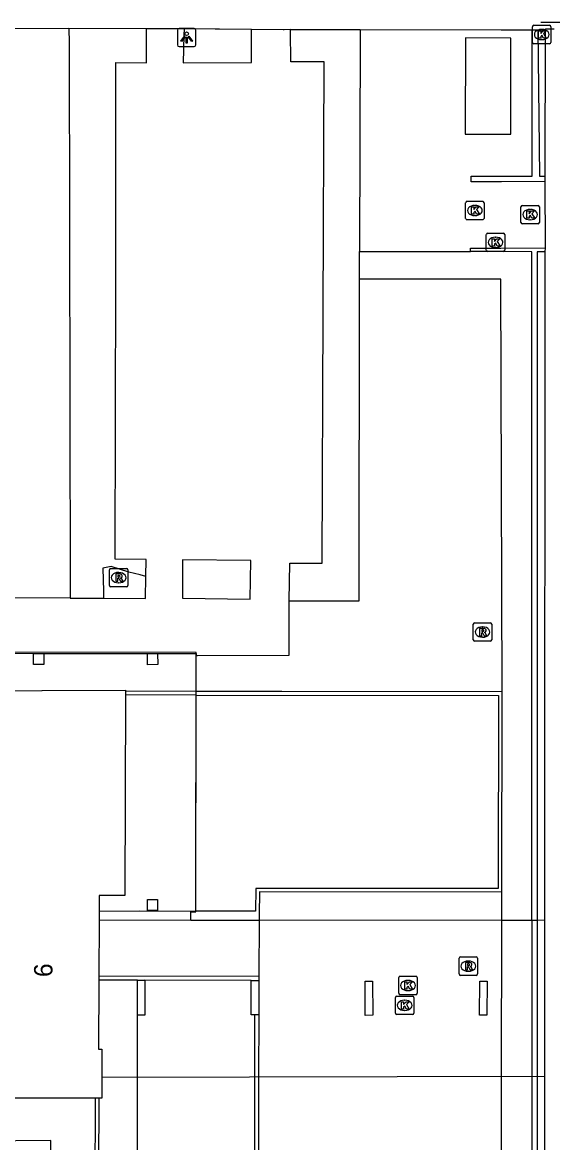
# Model space of a CAD drawing. Extents: x 161477 to 163040, y 383680 to 384868.
# Drawn here: x 161757.4 to 161786.3, y 384128.9 to 384189.9 of the extents above; entities that cross this region are included whole.
import ezdxf

# ---------------------------------------------------------------- set-up
doc = ezdxf.new("R2010")
doc.units = 0
for name, color, linetype in [('IMGEO_Groenvoorziening', 7, 'Continuous'), ('IMGEO_Kolk', 7, 'Continuous'), ('IMGEO_Lichtpunt', 7, 'Continuous'), ('IMGEO_Lijnafwatering', 7, 'Continuous'), ('IMGEO_Muur', 7, 'Continuous'), ('IMGEO_Pand', 7, 'Continuous'), ('IMGEO_Pand_nummerreeks', 7, 'Continuous'), ('IMGEO_Pand_overbouw', 7, 'Continuous'), ('IMGEO_Rijbaan_lokaal_gesloten', 7, 'Continuous'), ('IMGEO_Rijbaan_lokaal_open', 7, 'Continuous'), ('IMGEO_Rioolput', 7, 'Continuous'), ('IMGEO_Voetpad_gesloten', 7, 'Continuous'), ('IMGEO_Voetpad_open', 7, 'Continuous')]:
    doc.layers.add(name, color=color, linetype=linetype)

msp = doc.modelspace()

# ---------------------------------------------------------------- linework, layer by layer
at = {"layer": 'IMGEO_Groenvoorziening'}
for points in [[(161759.976, 384189.513), (161759.977, 384188.732), (161760.032, 384158.93), (161760.033, 384158.521)], [(161771.96, 384158.37), (161775.755, 384158.378), (161775.779, 384175.877)], [(161765.84, 384080.732), (161762.894, 384080.681), (161762.895, 384081.151), (161763.216, 384099.214), (161763.654, 384124.37), (161759.044, 384124.455), (161758.995, 384129.011), (161747.606, 384128.913), (161747.599, 384129.203)]]:
    msp.add_lwpolyline(points, dxfattribs=at)
at = {"layer": 'IMGEO_Kolk'}
for p, q in [((161785.189, 384188.766), (161785.189, 384189.618)), ((161785.264, 384189.692), (161786.116, 384189.692)), ((161786.19, 384189.618), (161786.19, 384188.766)), ((161785.7, 384188.912), (161785.675, 384188.912)), ((161785.677, 384189.472), (161785.702, 384189.472)), ((161786.116, 384188.692), (161785.264, 384188.692)), ((161781.553, 384179.19), (161781.553, 384180.042)), ((161781.628, 384180.116), (161782.48, 384180.116)), ((161782.041, 384179.896), (161782.066, 384179.896)), ((161782.554, 384180.042), (161782.554, 384179.19)), ((161784.562, 384178.969), (161784.562, 384179.821)), ((161784.637, 384179.895), (161785.489, 384179.895)), ((161785.563, 384179.821), (161785.563, 384178.969)), ((161782.064, 384179.336), (161782.039, 384179.336)), ((161785.05, 384179.675), (161785.075, 384179.675)), ((161782.48, 384179.116), (161781.628, 384179.116)), ((161785.489, 384178.895), (161784.637, 384178.895)), ((161785.073, 384179.115), (161785.048, 384179.115)), ((161782.677, 384177.454), (161782.677, 384178.306)), ((161782.752, 384178.38), (161783.604, 384178.38)), ((161783.165, 384178.16), (161783.19, 384178.16)), ((161783.678, 384178.306), (161783.678, 384177.454)), ((161783.604, 384177.38), (161782.752, 384177.38)), ((161783.188, 384177.6), (161783.163, 384177.6)), ((161777.916, 384137.022), (161777.916, 384137.874)), ((161777.991, 384137.948), (161778.843, 384137.948)), ((161778.404, 384137.728), (161778.429, 384137.728)), ((161778.917, 384137.874), (161778.917, 384137.022)), ((161778.427, 384137.168), (161778.402, 384137.168)), ((161777.734, 384135.941), (161777.734, 384136.793)), ((161777.809, 384136.867), (161778.661, 384136.867)), ((161778.843, 384136.948), (161777.991, 384136.948)), ((161778.222, 384136.647), (161778.247, 384136.647)), ((161778.735, 384136.793), (161778.735, 384135.941)), ((161778.661, 384135.867), (161777.809, 384135.867)), ((161778.245, 384136.087), (161778.22, 384136.087))]:
    msp.add_line(p, q, dxfattribs=at)
for points in [[(161785.189, 384188.766), (161785.189, 384189.618)], [(161785.264, 384189.692), (161786.116, 384189.692)], [(161786.19, 384189.618), (161786.19, 384188.766)], [(161785.51, 384189.392), (161785.633, 384189.392), (161785.633, 384189.241), (161785.763, 384189.392), (161785.927, 384189.392), (161785.781, 384189.241), (161785.934, 384188.992), (161785.782, 384188.992), (161785.697, 384189.156), (161785.633, 384189.089), (161785.633, 384188.992), (161785.51, 384188.992), (161785.51, 384189.392)], [(161786.116, 384188.692), (161785.264, 384188.692)], [(161781.553, 384179.19), (161781.553, 384180.042)], [(161781.628, 384180.116), (161782.48, 384180.116)], [(161781.874, 384179.816), (161781.997, 384179.816), (161781.997, 384179.665), (161782.127, 384179.816), (161782.291, 384179.816), (161782.145, 384179.665), (161782.298, 384179.416), (161782.146, 384179.416), (161782.061, 384179.58), (161781.997, 384179.513), (161781.997, 384179.416), (161781.874, 384179.416), (161781.874, 384179.816)], [(161782.554, 384180.042), (161782.554, 384179.19)], [(161784.562, 384178.969), (161784.562, 384179.821)], [(161784.637, 384179.895), (161785.489, 384179.895)], [(161785.563, 384179.821), (161785.563, 384178.969)], [(161784.883, 384179.595), (161785.006, 384179.595), (161785.006, 384179.444), (161785.136, 384179.595), (161785.3, 384179.595), (161785.154, 384179.444), (161785.307, 384179.195), (161785.155, 384179.195), (161785.07, 384179.359), (161785.006, 384179.292), (161785.006, 384179.195), (161784.883, 384179.195), (161784.883, 384179.595)], [(161782.48, 384179.116), (161781.628, 384179.116)], [(161785.489, 384178.895), (161784.637, 384178.895)], [(161782.677, 384177.454), (161782.677, 384178.306)], [(161782.752, 384178.38), (161783.604, 384178.38)], [(161782.998, 384178.08), (161783.121, 384178.08), (161783.121, 384177.929), (161783.251, 384178.08), (161783.415, 384178.08), (161783.269, 384177.929), (161783.422, 384177.68), (161783.27, 384177.68), (161783.185, 384177.844), (161783.121, 384177.777), (161783.121, 384177.68), (161782.998, 384177.68), (161782.998, 384178.08)], [(161783.678, 384178.306), (161783.678, 384177.454)], [(161783.604, 384177.38), (161782.752, 384177.38)], [(161777.916, 384137.022), (161777.916, 384137.874)], [(161777.991, 384137.948), (161778.843, 384137.948)], [(161778.917, 384137.874), (161778.917, 384137.022)], [(161778.237, 384137.648), (161778.36, 384137.648), (161778.36, 384137.497), (161778.49, 384137.648), (161778.654, 384137.648), (161778.508, 384137.497), (161778.661, 384137.248), (161778.509, 384137.248), (161778.424, 384137.412), (161778.36, 384137.345), (161778.36, 384137.248), (161778.237, 384137.248), (161778.237, 384137.648)], [(161777.734, 384135.941), (161777.734, 384136.793)], [(161777.809, 384136.867), (161778.661, 384136.867)], [(161778.843, 384136.948), (161777.991, 384136.948)], [(161778.055, 384136.567), (161778.178, 384136.567), (161778.178, 384136.416), (161778.308, 384136.567), (161778.472, 384136.567), (161778.326, 384136.416), (161778.479, 384136.167), (161778.327, 384136.167), (161778.242, 384136.331), (161778.178, 384136.264), (161778.178, 384136.167), (161778.055, 384136.167), (161778.055, 384136.567)], [(161778.735, 384136.793), (161778.735, 384135.941)], [(161778.661, 384135.867), (161777.809, 384135.867)]]:
    msp.add_lwpolyline(points, dxfattribs=at)
for centre, start, end in [((161785.266, 384189.616), 91.55205, 178.44795), ((161785.266, 384189.616), 91.55205, 178.44795), ((161786.114, 384189.616), 1.55205, 88.44795), ((161786.114, 384189.616), 1.55205, 88.44795), ((161785.266, 384188.768), 181.55205, 268.44795), ((161785.266, 384188.768), 181.55205, 268.44795), ((161786.114, 384188.768), 271.55205, 358.44795), ((161786.114, 384188.768), 271.55205, 358.44795), ((161781.63, 384180.04), 91.55205, 178.44795), ((161781.63, 384180.04), 91.55205, 178.44795), ((161782.478, 384180.04), 1.55205, 88.44795), ((161782.478, 384180.04), 1.55205, 88.44795), ((161784.639, 384179.819), 91.55205, 178.44795), ((161784.639, 384179.819), 91.55205, 178.44795), ((161785.487, 384179.819), 1.55205, 88.44795), ((161785.487, 384179.819), 1.55205, 88.44795), ((161781.63, 384179.192), 181.55205, 268.44795), ((161781.63, 384179.192), 181.55205, 268.44795), ((161782.478, 384179.192), 271.55205, 358.44795), ((161782.478, 384179.192), 271.55205, 358.44795), ((161784.639, 384178.971), 181.55205, 268.44795), ((161784.639, 384178.971), 181.55205, 268.44795), ((161785.487, 384178.971), 271.55205, 358.44795), ((161785.487, 384178.971), 271.55205, 358.44795), ((161782.754, 384178.304), 91.55205, 178.44795), ((161782.754, 384178.304), 91.55205, 178.44795), ((161783.602, 384178.304), 1.55205, 88.44795), ((161783.602, 384178.304), 1.55205, 88.44795), ((161782.754, 384177.456), 181.55205, 268.44795), ((161782.754, 384177.456), 181.55205, 268.44795), ((161783.602, 384177.456), 271.55205, 358.44795), ((161783.602, 384177.456), 271.55205, 358.44795), ((161777.993, 384137.872), 91.55205, 178.44795), ((161777.993, 384137.872), 91.55205, 178.44795), ((161778.841, 384137.872), 1.55205, 88.44795), ((161778.841, 384137.872), 1.55205, 88.44795), ((161777.811, 384136.791), 91.55205, 178.44795), ((161777.811, 384136.791), 91.55205, 178.44795), ((161777.993, 384137.024), 181.55205, 268.44795), ((161777.993, 384137.024), 181.55205, 268.44795), ((161778.659, 384136.791), 1.55205, 88.44795), ((161778.659, 384136.791), 1.55205, 88.44795), ((161778.841, 384137.024), 271.55205, 358.44795), ((161778.841, 384137.024), 271.55205, 358.44795), ((161777.811, 384135.943), 181.55205, 268.44795), ((161777.811, 384135.943), 181.55205, 268.44795), ((161778.659, 384135.943), 271.55205, 358.44795), ((161778.659, 384135.943), 271.55205, 358.44795)]:
    msp.add_arc(centre, 0.0765, start, end, dxfattribs=at)
for centre, major_axis, ratio, start_param, end_param in [((161785.676, 384189.192), (-0.387, 0.002), 0.722429, 4.712389, 7.853982), ((161785.701, 384189.192), (-0.39, 0.002), 0.717154, 1.570796, 4.712389), ((161782.04, 384179.616), (-0.387, 0.002), 0.722429, 4.712389, 7.853982), ((161782.065, 384179.616), (-0.39, 0.002), 0.717154, 1.570796, 4.712389), ((161785.049, 384179.395), (-0.387, 0.002), 0.722429, 4.712389, 7.853982), ((161785.074, 384179.395), (-0.39, 0.002), 0.717154, 1.570796, 4.712389), ((161783.164, 384177.88), (-0.387, 0.002), 0.722429, 4.712389, 7.853982), ((161783.189, 384177.88), (-0.39, 0.002), 0.717154, 1.570796, 4.712389), ((161778.403, 384137.448), (-0.387, 0.002), 0.722429, 4.712389, 7.853982), ((161778.428, 384137.448), (-0.39, 0.002), 0.717154, 1.570796, 4.712389), ((161778.221, 384136.367), (-0.387, 0.002), 0.722429, 4.712389, 7.853982), ((161778.246, 384136.367), (-0.39, 0.002), 0.717154, 1.570796, 4.712389)]:
    msp.add_ellipse(centre, major_axis=major_axis, ratio=ratio, start_param=start_param, end_param=end_param, dxfattribs=at)
at = {"layer": 'IMGEO_Lichtpunt'}
for p, q in [((161766.779, 384189.528), (161765.971, 384189.528)), ((161766.779, 384189.528), (161765.971, 384189.528)), ((161765.877, 384189.433), (161765.877, 384188.626)), ((161765.877, 384189.433), (161765.877, 384188.626)), ((161766.873, 384188.626), (161766.873, 384189.433)), ((161766.873, 384188.626), (161766.873, 384189.433)), ((161765.971, 384188.532), (161766.779, 384188.532)), ((161765.971, 384188.532), (161766.779, 384188.532))]:
    msp.add_line(p, q, dxfattribs=at)
for points in [[(161766.251, 384189.097), (161766.29, 384189.069), (161766.102, 384188.807), (161766.064, 384188.834), (161766.251, 384189.097)], [(161766.353, 384189.049), (161766.4, 384189.049), (161766.4, 384188.727), (161766.353, 384188.727), (161766.353, 384189.049)], [(161766.463, 384189.069), (161766.501, 384189.096), (161766.688, 384188.834), (161766.649, 384188.806), (161766.463, 384189.069)]]:
    msp.add_lwpolyline(points, dxfattribs=at)
msp.add_circle((161766.376, 384189.231), 0.0994, dxfattribs=at)
for centre, start, end in [((161765.971, 384189.433), 90, 180), ((161765.971, 384189.433), 90, 180), ((161766.779, 384189.433), 0, 90), ((161766.779, 384189.433), 0, 90), ((161765.971, 384188.626), 180, 270), ((161765.971, 384188.626), 180, 270), ((161766.779, 384188.626), 270, 0), ((161766.779, 384188.626), 270, 360)]:
    msp.add_arc(centre, 0.0946, start, end, dxfattribs=at)
at = {"layer": 'IMGEO_Lijnafwatering'}
msp.add_lwpolyline([(161802.26, 384189.851), (161785.646, 384189.847)], dxfattribs=at)
at = {"layer": 'IMGEO_Muur'}
for points in [[(161785.875, 384181.186), (161783.498, 384181.183), (161781.858, 384181.181), (161781.859, 384181.313), (161781.861, 384181.49), (161783.497, 384181.489), (161785.175, 384181.487), (161785.175, 384189.451)], [(161785.175, 384189.451), (161785.475, 384189.45)], [(161785.475, 384189.45), (161785.565, 384181.487), (161785.875, 384181.487)], [(161781.823, 384177.383), (161781.824, 384177.573), (161783.458, 384177.566), (161785.887, 384177.585)], [(161785.147, 384140.979), (161785.151, 384177.376), (161783.458, 384177.38), (161781.823, 384177.383)], [(161785.886, 384177.374), (161785.451, 384177.375), (161785.447, 384140.979)], [(161766.888, 384153.253), (161763.051, 384153.259)], [(161766.889, 384153.453), (161763.052, 384153.459)], [(161766.888, 384153.253), (161783.34, 384153.229), (161783.324, 384142.729), (161770.131, 384142.734), (161770.124, 384141.486), (161766.875, 384141.495)], [(161783.538, 384153.428), (161771.553, 384153.446), (161767.871, 384153.452), (161766.889, 384153.453)], [(161783.525, 384142.532), (161783.538, 384153.428)], [(161783.525, 384142.532), (161770.33, 384142.536), (161770.315, 384141.296), (161770.314, 384141.003)], [(161761.611, 384141.494), (161763.811, 384141.504), (161766.875, 384141.495)], [(161761.61, 384141.018), (161766.597, 384141.01), (161770.314, 384141.003)], [(161785.147, 384140.979), (161785.146, 384132.516), (161785.146, 384129.986), (161785.111, 384078.07), (161784.004, 384078.073), (161783.984, 384076.077), (161785.095, 384076.066), (161785.092, 384072.311), (161785.392, 384072.311)], [(161785.447, 384140.979), (161785.147, 384140.979)], [(161785.447, 384140.979), (161785.446, 384132.517), (161785.446, 384129.986), (161785.405, 384078.07), (161785.825, 384078.07)], [(161763.697, 384137.73), (161761.595, 384137.732)], [(161770.298, 384137.963), (161761.596, 384137.932)], [(161769.888, 384137.723), (161764.097, 384137.729)], [(161770.298, 384137.963), (161770.298, 384137.723)], [(161770.077, 384127.464), (161770.084, 384132.48), (161770.089, 384135.843)], [(161770.295, 384135.843), (161770.29, 384132.481), (161770.213, 384080.772)], [(161761.398, 384131.31), (161761.389, 384126.458), (161765.899, 384126.429), (161765.84, 384080.732)], [(161761.598, 384131.31), (161761.575, 384127.453)]]:
    msp.add_lwpolyline(points, dxfattribs=at)
at = {"layer": 'IMGEO_Pand'}
for points in [[(161785.894, 384189.449), (161785.894, 384189.502), (161786.374, 384189.501)], [(161785.875, 384181.487), (161785.894, 384189.449)], [(161785.875, 384181.186), (161785.875, 384181.303), (161785.875, 384181.487)], [(161785.887, 384177.585), (161785.875, 384181.186)], [(161785.825, 384078.07), (161785.858, 384132.518), (161785.863, 384140.978), (161785.886, 384177.374)], [(161785.886, 384177.374), (161785.887, 384177.585)], [(161758.052, 384155.506), (161758.603, 384155.507)], [(161758.603, 384155.507), (161758.604, 384154.907), (161758.053, 384154.906), (161758.052, 384155.506)], [(161764.245, 384155.504), (161764.799, 384155.505)], [(161764.799, 384155.505), (161764.8, 384154.905), (161764.246, 384154.904), (161764.245, 384155.504)], [(161740.363, 384153.423), (161763.052, 384153.523), (161763.052, 384153.459)], [(161763.051, 384153.259), (161763.015, 384142.34), (161761.615, 384142.346), (161761.611, 384141.494)], [(161763.052, 384153.459), (161763.051, 384153.259)], [(161764.798, 384142.118), (161764.798, 384141.527), (161764.248, 384141.527), (161764.248, 384142.118), (161764.798, 384142.118)], [(161761.611, 384141.494), (161761.611, 384141.303), (161761.61, 384141.018)], [(161761.61, 384141.018), (161761.596, 384137.932)], [(161761.595, 384137.732), (161761.579, 384133.98), (161761.759, 384133.98), (161761.765, 384132.46), (161761.768, 384131.31), (161761.598, 384131.31)], [(161761.596, 384137.932), (161761.595, 384137.732)], [(161763.696, 384135.837), (161763.697, 384137.73)], [(161764.097, 384137.729), (161764.096, 384135.837), (161763.696, 384135.837)], [(161763.697, 384137.73), (161764.097, 384137.729)], [(161770.089, 384135.843), (161769.885, 384135.843), (161769.888, 384137.723)], [(161769.888, 384137.723), (161770.298, 384137.723)], [(161770.298, 384137.723), (161770.295, 384135.843)], [(161776.089, 384137.691), (161776.489, 384137.692), (161776.495, 384135.825), (161776.095, 384135.824), (161776.089, 384137.691)], [(161782.307, 384135.832), (161782.315, 384137.684), (161782.715, 384137.682), (161782.707, 384135.83), (161782.307, 384135.832)], [(161770.295, 384135.843), (161770.089, 384135.843)], [(161761.398, 384131.31), (161747.578, 384131.312)], [(161761.598, 384131.31), (161761.398, 384131.31)]]:
    msp.add_lwpolyline(points, dxfattribs=at)
at = {"layer": 'IMGEO_Pand_overbouw'}
msp.add_lwpolyline([(161740.284, 384153.423), (161763.052, 384153.523), (161763.052, 384153.459), (161763.051, 384153.259), (161763.015, 384142.34), (161761.615, 384142.346), (161761.611, 384141.494), (161761.611, 384141.303), (161761.61, 384141.018), (161761.596, 384137.932), (161761.595, 384137.732), (161761.579, 384133.98), (161761.759, 384133.98), (161761.765, 384132.46), (161785.858, 384132.518), (161785.863, 384140.978), (161766.597, 384141.01), (161766.601, 384141.299), (161766.604, 384141.462), (161766.875, 384141.46), (161766.891, 384155.558), (161737.37, 384155.593)], dxfattribs=at)
at = {"layer": 'IMGEO_Rijbaan_lokaal_gesloten'}
for points in [[(161729.725, 384182.49), (161732.479, 384184.27), (161740.985, 384188.366), (161743.11, 384189.23), (161744.828, 384189.533), (161759.976, 384189.513)], [(161764.184, 384189.507), (161759.976, 384189.513)], [(161766.239, 384189.502), (161764.184, 384189.507)], [(161769.899, 384189.471), (161768.161, 384189.487), (161767.92, 384189.485), (161766.239, 384189.502)], [(161772.016, 384189.456), (161771.683, 384189.455), (161771.619, 384189.455), (161769.899, 384189.471)], [(161772.016, 384189.456), (161775.806, 384189.472)], [(161775.806, 384189.472), (161783.481, 384189.447), (161785.175, 384189.451)], [(161785.475, 384189.45), (161785.894, 384189.449)]]:
    msp.add_lwpolyline(points, dxfattribs=at)
at = {"layer": 'IMGEO_Rijbaan_lokaal_open'}
for points in [[(161775.806, 384189.472), (161775.806, 384189.253), (161775.782, 384177.394)], [(161784.014, 384188.997), (161781.542, 384189.009), (161781.529, 384183.775), (161783.492, 384183.775), (161784.013, 384183.775), (161784.014, 384188.997)], [(161775.782, 384177.394), (161781.823, 384177.383)]]:
    msp.add_lwpolyline(points, dxfattribs=at)
at = {"layer": 'IMGEO_Rioolput'}
for p, q in [((161762.179, 384159.214), (161762.179, 384160.066)), ((161762.254, 384160.14), (161763.106, 384160.14)), ((161762.667, 384159.92), (161762.692, 384159.92)), ((161763.18, 384160.066), (161763.18, 384159.214)), ((161763.106, 384159.14), (161762.254, 384159.14)), ((161762.69, 384159.36), (161762.665, 384159.36)), ((161781.969, 384156.254), (161781.969, 384157.106)), ((161782.044, 384157.18), (161782.896, 384157.18)), ((161782.457, 384156.96), (161782.482, 384156.96)), ((161782.97, 384157.106), (161782.97, 384156.254)), ((161782.896, 384156.18), (161782.044, 384156.18)), ((161782.48, 384156.4), (161782.455, 384156.4)), ((161781.199, 384138.074), (161781.199, 384138.926)), ((161781.274, 384139), (161782.126, 384139)), ((161782.2, 384138.926), (161782.2, 384138.074)), ((161781.687, 384138.78), (161781.712, 384138.78)), ((161782.126, 384138), (161781.274, 384138)), ((161781.71, 384138.22), (161781.685, 384138.22))]:
    msp.add_line(p, q, dxfattribs=at)
for points in [[(161762.179, 384159.214), (161762.179, 384160.066)], [(161762.254, 384160.14), (161763.106, 384160.14)], [(161762.768, 384159.838), (161762.516, 384159.84), (161762.516, 384159.44)], [(161762.694, 384159.759), (161762.64, 384159.759), (161762.64, 384159.678)], [(161762.64, 384159.678), (161762.692, 384159.678)], [(161763.18, 384160.066), (161763.18, 384159.214)], [(161763.106, 384159.14), (161762.254, 384159.14)], [(161762.516, 384159.44), (161762.64, 384159.44), (161762.64, 384159.602), (161762.651, 384159.602)], [(161762.698, 384159.573), (161762.769, 384159.44), (161762.909, 384159.44), (161762.844, 384159.566)], [(161781.969, 384156.254), (161781.969, 384157.106)], [(161782.044, 384157.18), (161782.896, 384157.18)], [(161782.558, 384156.878), (161782.306, 384156.88), (161782.306, 384156.48)], [(161782.306, 384156.48), (161782.43, 384156.48), (161782.43, 384156.642), (161782.441, 384156.642)], [(161782.484, 384156.799), (161782.43, 384156.799), (161782.43, 384156.718)], [(161782.43, 384156.718), (161782.482, 384156.718)], [(161782.488, 384156.613), (161782.559, 384156.48), (161782.699, 384156.48), (161782.634, 384156.606)], [(161782.97, 384157.106), (161782.97, 384156.254)], [(161782.896, 384156.18), (161782.044, 384156.18)], [(161781.199, 384138.074), (161781.199, 384138.926)], [(161781.274, 384139), (161782.126, 384139)], [(161782.2, 384138.926), (161782.2, 384138.074)], [(161781.788, 384138.698), (161781.536, 384138.7), (161781.536, 384138.3)], [(161781.536, 384138.3), (161781.66, 384138.3), (161781.66, 384138.462), (161781.671, 384138.462)], [(161781.714, 384138.619), (161781.66, 384138.619), (161781.66, 384138.538)], [(161781.66, 384138.538), (161781.712, 384138.538)], [(161781.718, 384138.433), (161781.789, 384138.3), (161781.929, 384138.3), (161781.864, 384138.426)], [(161782.126, 384138), (161781.274, 384138)]]:
    msp.add_lwpolyline(points, dxfattribs=at)
for centre, radius, start, end in [((161762.256, 384160.064), 0.0765, 91.55205, 178.44795), ((161762.256, 384160.064), 0.0765, 91.55205, 178.44795), ((161762.676, 384159.867), 0.19, 274.7715, 282.96867), ((161762.7, 384159.663), 0.0964, 77.00612, 93.18647), ((161762.714, 384159.72), 0.0378, 276.66336, 79.67722), ((161762.767, 384159.728), 0.109, 350.36119, 89.41601), ((161762.765, 384159.728), 0.112, 277.58423, 350.98172), ((161763.104, 384160.064), 0.0765, 1.55205, 88.44795), ((161763.104, 384160.064), 0.0765, 1.55205, 88.44795), ((161762.256, 384159.216), 0.0765, 181.55205, 268.44795), ((161762.256, 384159.216), 0.0765, 181.55205, 268.44795), ((161762.65, 384159.549), 0.0533, 26.02933, 88.69889), ((161762.749, 384159.513), 0.108, 29.51342, 73.79051), ((161763.104, 384159.216), 0.0765, 271.55205, 358.44795), ((161763.104, 384159.216), 0.0765, 271.55205, 358.44795), ((161782.046, 384157.104), 0.0765, 91.55205, 178.44795), ((161782.046, 384157.104), 0.0765, 91.55205, 178.44795), ((161782.44, 384156.589), 0.0533, 26.02933, 88.69889), ((161782.466, 384156.907), 0.19, 274.7715, 282.96867), ((161782.49, 384156.703), 0.0964, 77.00612, 93.18647), ((161782.504, 384156.76), 0.0378, 276.66336, 79.67722), ((161782.557, 384156.768), 0.109, 350.36119, 89.41601), ((161782.555, 384156.768), 0.112, 277.58423, 350.98172), ((161782.539, 384156.553), 0.108, 29.51342, 73.79051), ((161782.894, 384157.104), 0.0765, 1.55205, 88.44795), ((161782.894, 384157.104), 0.0765, 1.55205, 88.44795), ((161782.046, 384156.256), 0.0765, 181.55205, 268.44795), ((161782.046, 384156.256), 0.0765, 181.55205, 268.44795), ((161782.894, 384156.256), 0.0765, 271.55205, 358.44795), ((161782.894, 384156.256), 0.0765, 271.55205, 358.44795), ((161781.276, 384138.924), 0.0765, 91.55205, 178.44795), ((161781.276, 384138.924), 0.0765, 91.55205, 178.44795), ((161782.124, 384138.924), 0.0765, 1.55205, 88.44795), ((161782.124, 384138.924), 0.0765, 1.55205, 88.44795), ((161781.67, 384138.409), 0.0533, 26.02933, 88.69889), ((161781.696, 384138.727), 0.19, 274.7715, 282.96867), ((161781.72, 384138.523), 0.0964, 77.00612, 93.18647), ((161781.734, 384138.58), 0.0378, 276.66336, 79.67722), ((161781.787, 384138.588), 0.109, 350.36119, 89.41601), ((161781.785, 384138.588), 0.112, 277.58423, 350.98172), ((161781.769, 384138.373), 0.108, 29.51342, 73.79051), ((161781.276, 384138.076), 0.0765, 181.55205, 268.44795), ((161781.276, 384138.076), 0.0765, 181.55205, 268.44795), ((161782.124, 384138.076), 0.0765, 271.55205, 358.44795), ((161782.124, 384138.076), 0.0765, 271.55205, 358.44795)]:
    msp.add_arc(centre, radius, start, end, dxfattribs=at)
for centre, major_axis, ratio, start_param, end_param in [((161762.666, 384159.64), (-0.387, 0.002), 0.722429, 4.712389, 7.853982), ((161762.691, 384159.64), (-0.39, 0.002), 0.717154, 1.570796, 4.712389), ((161782.456, 384156.68), (-0.387, 0.002), 0.722429, 4.712389, 7.853982), ((161782.481, 384156.68), (-0.39, 0.002), 0.717154, 1.570796, 4.712389), ((161781.686, 384138.5), (-0.387, 0.002), 0.722429, 4.712389, 7.853982), ((161781.711, 384138.5), (-0.39, 0.002), 0.717154, 1.570796, 4.712389)]:
    msp.add_ellipse(centre, major_axis=major_axis, ratio=ratio, start_param=start_param, end_param=end_param, dxfattribs=at)
at = {"layer": 'IMGEO_Voetpad_gesloten'}
for points in [[(161764.161, 384159.707), (161763.845, 384159.784), (161763.236, 384159.931), (161762.278, 384160.241), (161761.824, 384160.161), (161761.847, 384158.903), (161761.855, 384158.515)], [(161761.855, 384158.515), (161764.139, 384158.508), (161764.161, 384159.707)], [(161783.522, 384140.982), (161783.525, 384142.532)], [(161783.522, 384140.982), (161770.314, 384141.003)]]:
    msp.add_lwpolyline(points, dxfattribs=at)
at = {"layer": 'IMGEO_Voetpad_open'}
for points in [[(161764.161, 384159.707), (161764.178, 384160.618), (161762.485, 384160.644), (161762.518, 384175.954), (161762.517, 384187.669), (161764.194, 384187.66), (161764.185, 384189.286), (161764.184, 384189.507)], [(161766.239, 384189.502), (161766.23, 384189.161), (161766.192, 384187.658), (161769.898, 384187.673), (161769.899, 384189.471)], [(161771.96, 384158.37), (161771.986, 384160.436), (161773.754, 384160.426), (161773.848, 384187.698), (161772.046, 384187.714), (161772.018, 384189.369), (161772.016, 384189.456)], [(161775.779, 384175.877), (161775.782, 384177.394)], [(161783.538, 384153.428), (161783.463, 384175.882), (161781.842, 384175.881), (161775.779, 384175.877)], [(161769.861, 384160.566), (161766.156, 384160.601), (161766.15, 384158.515), (161769.834, 384158.477), (161769.861, 384160.566)], [(161760.033, 384158.521), (161734.619, 384158.605), (161723.254, 384158.616)], [(161760.033, 384158.521), (161761.855, 384158.515)], [(161766.891, 384155.412), (161766.969, 384155.412), (161771.952, 384155.422), (161771.96, 384158.37)], [(161752.409, 384155.523), (161758.052, 384155.506)], [(161758.603, 384155.507), (161764.245, 384155.504)], [(161764.799, 384155.505), (161766.891, 384155.509), (161766.891, 384155.412)], [(161766.889, 384153.453), (161766.891, 384155.412)], [(161766.875, 384141.495), (161766.888, 384153.253)], [(161770.314, 384141.003), (161770.298, 384137.963)], [(161783.384, 384061.717), (161783.399, 384075.023), (161782.399, 384075.02), (161782.387, 384079.036), (161783.387, 384079.036), (161783.503, 384132.512), (161783.522, 384140.982)], [(161785.147, 384140.979), (161783.522, 384140.982)], [(161763.707, 384127.456), (161763.702, 384131.658), (161763.701, 384132.465), (161763.696, 384135.837)]]:
    msp.add_lwpolyline(points, dxfattribs=at)

# ---------------------------------------------------------------- texts
at = {"layer": 'IMGEO_Pand_nummerreeks'}
msp.add_text('6', height=1, rotation=89.75384, dxfattribs=at).set_placement((161759.076, 384137.903))

doc.saveas('drawing.dxf')
